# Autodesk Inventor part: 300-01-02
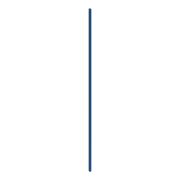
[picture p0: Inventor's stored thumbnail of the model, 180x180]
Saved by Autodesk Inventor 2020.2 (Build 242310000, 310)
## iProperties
Created: 2014-10
Part Number: 300-01-02
Material: Stal
Document SubType Name: Modeling
Designer: F.Stasiak
Density: 7.85 g/cm^3
Appearance: Cyjan
Catalog Web Link: www.expertbooks.pl
Manager: www.cadconsulting.pl
Company: Fabian Stasiak CAD Consulting
Author: F.Stasiak
Subject: Zbiór ćwiczeń. Autodesk Inventor 2020. Kurs Professional
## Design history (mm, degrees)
sketch "Szkic1"
  geometry: L1 (-12, -5)-(0, -5); L2 (0, -5)-(0, 5); L3 (0, 5)-(-12, 5); L4 (-12, 5)-(-12, -5); L5 (0, -1.5)-(-4, -1.5); L6 (-4, -1.5)-(-4, 1.5); L7 (-4, 1.5)-(0, 1.5); 3 further points
  constraints: 14 end point, 3 perpendicular, 2 horizontal, 2 midpoint, 2 parallel, 2 point on line, 1 coincident, 1 horizontal alignment
  dimensions: "d0" = 12 distance of L3.end L2.end; "d1" = 10 distance of L2.end L1.end; "d2" = 3 distance of L5.end L6.end; "d3" = 4 distance of L6.end L7.end
extrude "Wyciągnięcie proste1" new body sketch "Szkic1" distance "d4" = 1200; taper "d5" = 0 deg
node "Bryła1"
